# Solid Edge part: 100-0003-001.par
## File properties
Title: 100-0003-00.par
Author: rtconerl
Template: NORMMET.PAR
Last saved by: jccrumbl
Revision: 46
Application: Solid Edge
Revision: A
Teamcenter Item Type: Item
Accuracy: 0.99
TC Engineering Description: Valve Cap
TC_ImportTime: 2008-07-08
PartType: -
Last Saved Version: -
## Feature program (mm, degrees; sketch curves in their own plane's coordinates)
pattern "PatternOccurrence_1"
pattern "unnamed Pattern 1"
pattern "unnamed Pattern 2"
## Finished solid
Body 1: solid body, 11 faces, 22 edges, 8 vertices.
  Faces by surface: cylinder 7, plane 3, sphere 1
  Edges by curve: circle 12, line 6, intersection 4
Bounding box of the edges (mm; curved faces can reach further): 60.000 x 25.981 x 59.580, from (-30, 3.7054, -30) to (30, 29.6862, 29.5804).
Cylindrical faces by radius (mm): R1.5 x4, R7.5 x2, R15 x1
Spherical faces by radius (mm): R30 x1
Planar faces by outward normal: +z 1, -y 2
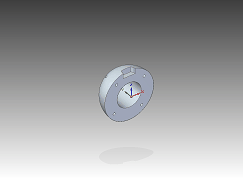
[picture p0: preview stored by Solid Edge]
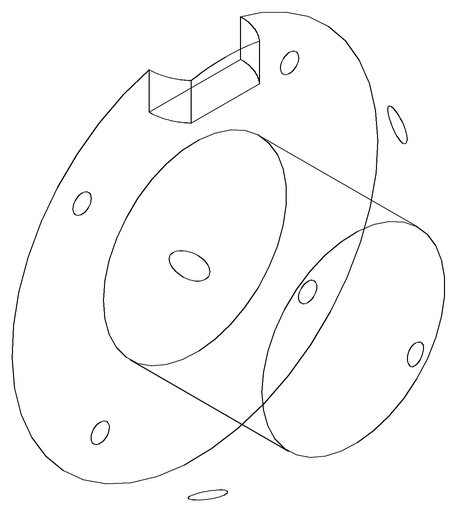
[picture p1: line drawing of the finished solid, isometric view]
